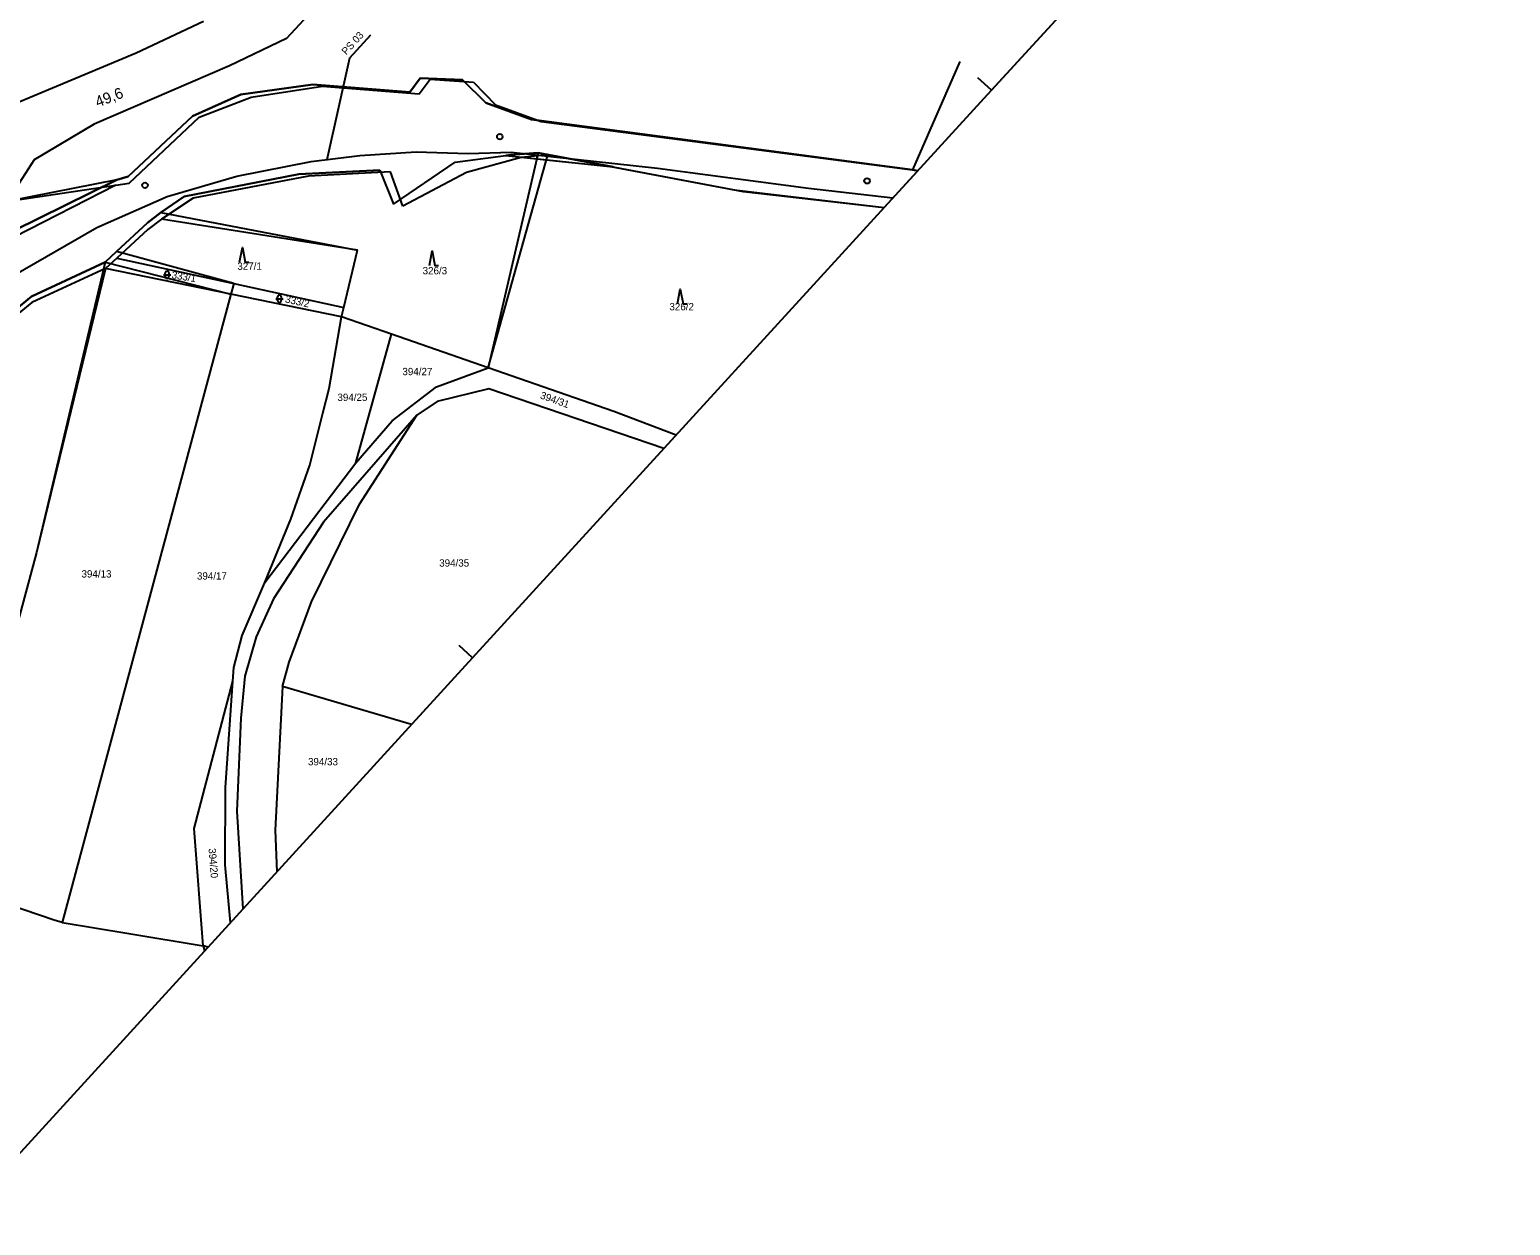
# Model space of a CAD drawing. Extents: x -678683 to -677755, y -1006946 to -1005971.
# Drawn here: x -678159.6 to -677755.1, y -1006636.4 to -1006309.9 of the extents above; entities that cross this region are included whole.
import ezdxf

# ---------------------------------------------------------------- set-up
doc = ezdxf.new("R2010")
doc.units = 0
for name, color, linetype in [('Default', 7, 'Continuous'), ('I_2_4_předběžný_vykres - Dočasný zábor - do 1 roku - PUPFL', 7, 'Continuous'), ('I_2_4_předběžný_vykres - SŽDC', 7, 'Continuous'), ('I_2_4_předběžný_vykres - VBř', 7, 'Continuous'), ('kilometráž - Vrstva 7', 7, 'Continuous'), ('koor - SSZT_nové', 7, 'Continuous'), ('MapaKN - Mladejov+Strelec_dosavani+nova_situace - Vrstva 1', 7, 'Continuous'), ('MapaKN - Mladejov+Strelec_dosavani+nova_situace - Vrstva 11', 7, 'Continuous'), ('MapaKN - Mladejov+Strelec_dosavani+nova_situace - Vrstva 18', 7, 'Continuous'), ('MapaKN - Mladejov+Strelec_dosavani+nova_situace - Vrstva 25', 7, 'Continuous'), ('MapaKN - původní vrstava 1', 7, 'Continuous'), ('popis', 7, 'Continuous'), ('ramy - Sekce lichá', 7, 'Continuous'), ('rozpiska - rámy', 7, 'Continuous')]:
    doc.layers.add(name, color=color, linetype=linetype)

msp = doc.modelspace()

# ---------------------------------------------------------------- linework, layer by layer
at = {"layer": 'Default'}
msp.add_line((-677896.87, -1006326.45), (-677755.13, -1006171.5), dxfattribs=at)
at = {"layer": 'I_2_4_předběžný_vykres - Dočasný zábor - do 1 roku - PUPFL'}
for p, q in [((-678028.13, -1006344.03), (-678029.55, -1006344.22)), ((-678020.64, -1006343.54), (-678028.13, -1006344.03)), ((-678021.01, -1006345.14), (-678020.64, -1006343.54)), ((-678020.64, -1006343.54), (-678021.01, -1006345.14)), ((-678000.24, -1006347.39), (-678020.64, -1006343.54)), ((-678029.55, -1006344.22), (-678021.01, -1006345.14)), ((-678021.01, -1006345.14), (-678000.24, -1006347.39))]:
    msp.add_line(p, q, dxfattribs=at)
msp.add_lwpolyline([(-678029.55, -1006344.22), (-678000.24, -1006347.39)], dxfattribs=at)
at = {"layer": 'I_2_4_předběžný_vykres - SŽDC'}
for p, q in [((-678052.89, -1006323.12), (-678055.78, -1006326.94)), ((-678041.39, -1006323.57), (-678052.89, -1006323.12)), ((-678034.98, -1006329.89), (-678041.39, -1006323.57)), ((-678101.88, -1006327.62), (-678115.07, -1006333.55)), ((-678082.23, -1006324.86), (-678101.88, -1006327.62)), ((-678055.78, -1006326.94), (-678082.23, -1006324.86)), ((-678022.51, -1006334.41), (-678034.98, -1006329.89)), ((-678115.07, -1006333.55), (-678132.64, -1006350.02)), ((-677918.4, -1006348.18), (-678022.51, -1006334.41)), ((-678043.36, -1006346.1), (-678028.13, -1006344.03)), ((-678028.13, -1006344.03), (-678020.64, -1006343.54)), ((-678020.64, -1006343.54), (-677967.17, -1006353.62)), ((-678060.24, -1006357.55), (-678043.36, -1006346.1)), ((-677916.96, -1006348.41), (-677918.4, -1006348.18)), ((-678135.76, -1006350.92), (-678163.98, -1006364.86)), ((-678132.64, -1006350.02), (-678135.76, -1006350.92)), ((-678117.34, -1006355.48), (-678086.04, -1006349.39)), ((-678086.04, -1006349.39), (-678063.96, -1006348.27)), ((-678063.96, -1006348.27), (-678060.24, -1006357.55)), ((-677926.18, -1006358.49), (-677916.96, -1006348.41)), ((-678123.78, -1006359.86), (-678117.34, -1006355.48)), ((-677967.17, -1006353.62), (-677926.18, -1006358.49)), ((-678127.43, -1006362.62), (-678123.78, -1006359.86)), ((-678135.88, -1006370.51), (-678127.43, -1006362.62)), ((-678138.95, -1006373.37), (-678135.88, -1006370.51)), ((-678159.12, -1006382.74), (-678138.95, -1006373.37)), ((-678187.52, -1006406.01), (-678159.12, -1006382.74))]:
    msp.add_line(p, q, dxfattribs=at)
at = {"layer": 'I_2_4_předběžný_vykres - VBř'}
msp.add_lwpolyline([(-678029.55, -1006344.22), (-678000.24, -1006347.39), (-678020.64, -1006343.54)], close=True, dxfattribs=at)
at = {"layer": 'kilometráž - Vrstva 7'}
for centre in [(-678031.17, -1006339.12), (-678128.06, -1006352.39), (-677930.85, -1006351.19)]:
    msp.add_circle(centre, 0.75, dxfattribs=at)
at = {"layer": 'koor - SSZT_nové'}
msp.add_lwpolyline([(-678199.43, -1006408.27), (-678188.69, -1006396.92), (-678166.33, -1006378.36), (-678141.21, -1006363.9), (-678122.02, -1006355.42), (-678102.99, -1006349.89), (-678082.69, -1006345.92), (-678069.35, -1006344.3), (-678054.02, -1006343.3), (-678039.76, -1006343.69), (-678028.1, -1006343.37), (-677988.11, -1006347.69), (-677946.88, -1006353.16), (-677923.77, -1006355.85)], dxfattribs=at)
at = {"layer": 'MapaKN - Mladejov+Strelec_dosavani+nova_situace - Vrstva 1'}
for points in [[(-678078.93, -1006300.97), (-678089.46, -1006312.29)], [(-678112.1, -1006307.67), (-678130.46, -1006316.3)], [(-678089.46, -1006312.29), (-678105.02, -1006319.82)], [(-678130.46, -1006316.3), (-678180.18, -1006337.1)], [(-678105.02, -1006319.82), (-678141.98, -1006335.73)], [(-677905.49, -1006318.57), (-677918.4, -1006348.18)], [(-678141.98, -1006335.73), (-678158.36, -1006345.46)], [(-678158.36, -1006345.46), (-678162.46, -1006351.78)], [(-677918.4, -1006348.18), (-677916.96, -1006348.41)], [(-678073.77, -1006385.75), (-678070.06, -1006370.08)], [(-678103.81, -1006379.22), (-678104.6, -1006382.15)], [(-678103.81, -1006379.22), (-678073.77, -1006385.75)], [(-678104.6, -1006382.15), (-678150.72, -1006553.63)], [(-678074.39, -1006388.34), (-678104.6, -1006382.15)], [(-678077.74, -1006407.83), (-678074.39, -1006388.34)], [(-678074.39, -1006388.34), (-678073.77, -1006385.75)], [(-678060.76, -1006393.07), (-678074.39, -1006388.34)], [(-678070.46, -1006428.16), (-678060.76, -1006393.07)], [(-678034.32, -1006402.24), (-678060.76, -1006393.07)], [(-678048.48, -1006407.43), (-678034.32, -1006402.24)], [(-678000, -1006414.15), (-678034.32, -1006402.24)], [(-678079.52, -1006414.56), (-678077.74, -1006407.83)], [(-678060.57, -1006416.67), (-678048.48, -1006407.43)], [(-678034.19, -1006407.98), (-678048.29, -1006411.44)], [(-677986.33, -1006424.24), (-678034.19, -1006407.98)], [(-678048.29, -1006411.44), (-678053.78, -1006415.18)], [(-678083.07, -1006428.79), (-678079.52, -1006414.56)], [(-678053.78, -1006415.18), (-678079.32, -1006444.33)], [(-678070.46, -1006428.16), (-678060.57, -1006416.67)], [(-678069.44, -1006439.48), (-678053.78, -1006415.18)], [(-677982.96, -1006420.57), (-678000, -1006414.15)], [(-678095.31, -1006460.84), (-678070.46, -1006428.16)], [(-678088.28, -1006443.53), (-678083.07, -1006428.79)], [(-678082.58, -1006466.13), (-678069.44, -1006439.48)], [(-678095.31, -1006460.84), (-678088.28, -1006443.53)], [(-678079.32, -1006444.33), (-678092.98, -1006465.3)], [(-678157.68, -1006452.66), (-678182.07, -1006543.07)], [(-678101.52, -1006475.32), (-678095.31, -1006460.84)], [(-678092.98, -1006465.3), (-678097.72, -1006475.69)], [(-678088.72, -1006482.62), (-678082.58, -1006466.13)], [(-678103.84, -1006484.04), (-678101.52, -1006475.32)], [(-678097.72, -1006475.69), (-678100.8, -1006486.38)], [(-678104.1, -1006487.79), (-678103.84, -1006484.04)], [(-678090.56, -1006489.19), (-678088.72, -1006482.62)], [(-678114.62, -1006528.01), (-678104.1, -1006487.79)], [(-678106.13, -1006516.77), (-678104.1, -1006487.79)], [(-678100.8, -1006486.38), (-678101.88, -1006497.89)], [(-678090.56, -1006489.19), (-678092.52, -1006528.43)], [(-678055.31, -1006499.65), (-678090.56, -1006489.19)], [(-678101.88, -1006497.89), (-678102.96, -1006523.31)], [(-678106.14, -1006537.95), (-678106.13, -1006516.77)], [(-678102.96, -1006523.31), (-678101.31, -1006549.94)], [(-678112.16, -1006560.07), (-678114.62, -1006528.01)], [(-678092.52, -1006528.43), (-678092.09, -1006539.86)], [(-678104.68, -1006553.63), (-678106.14, -1006537.95)], [(-678152.85, -1006553.07), (-678182.07, -1006543.07)], [(-678150.72, -1006553.63), (-678152.85, -1006553.07)], [(-678150.72, -1006553.63), (-678132.51, -1006556.69)], [(-678132.51, -1006556.69), (-678112.16, -1006560.07)], [(-678110.84, -1006560.36), (-678112.16, -1006560.07)], [(-678112.16, -1006560.07), (-678111.79, -1006561.4)]]:
    msp.add_lwpolyline(points, dxfattribs=at)
at = {"layer": 'MapaKN - Mladejov+Strelec_dosavani+nova_situace - Vrstva 11'}
msp.add_line((-678138.95, -1006373.37), (-678157.68, -1006452.66), dxfattribs=at)
for points in [[(-678055.78, -1006326.94), (-678052.89, -1006323.12)], [(-678052.89, -1006323.12), (-678041.39, -1006323.57)], [(-678041.39, -1006323.57), (-678034.98, -1006329.89)], [(-678115.07, -1006333.55), (-678101.88, -1006327.62)], [(-678101.88, -1006327.62), (-678082.23, -1006324.86)], [(-678082.23, -1006324.86), (-678055.78, -1006326.94)], [(-678034.98, -1006329.89), (-678022.51, -1006334.41)], [(-678132.64, -1006350.02), (-678115.07, -1006333.55)], [(-678022.51, -1006334.41), (-677918.4, -1006348.18)], [(-678043.36, -1006346.1), (-678028.13, -1006344.03)], [(-678020.64, -1006343.54), (-678034.32, -1006402.24)], [(-678028.13, -1006344.03), (-678020.64, -1006343.54)], [(-678020.64, -1006343.54), (-677967.17, -1006353.62)], [(-678060.24, -1006357.55), (-678043.36, -1006346.1)], [(-678135.76, -1006350.92), (-678165.35, -1006356.69)], [(-678163.98, -1006364.86), (-678135.76, -1006350.92)], [(-678135.76, -1006350.92), (-678132.64, -1006350.02)], [(-678086.04, -1006349.39), (-678117.34, -1006355.48)], [(-678063.96, -1006348.27), (-678086.04, -1006349.39)], [(-678063.96, -1006348.27), (-678060.24, -1006357.55)], [(-678117.34, -1006355.48), (-678123.78, -1006359.86)], [(-677967.17, -1006353.62), (-677926.18, -1006358.49)], [(-678123.78, -1006359.86), (-678127.43, -1006362.62)], [(-678123.78, -1006359.86), (-678070.06, -1006370.08)], [(-678127.43, -1006362.62), (-678135.88, -1006370.51)], [(-678135.88, -1006370.51), (-678138.95, -1006373.37)], [(-678103.81, -1006379.22), (-678135.88, -1006370.51)], [(-678138.95, -1006373.37), (-678159.12, -1006382.74)], [(-678138.95, -1006373.37), (-678104.6, -1006382.15)], [(-678159.12, -1006382.74), (-678187.52, -1006406.01)]]:
    msp.add_lwpolyline(points, dxfattribs=at)
at = {"layer": 'MapaKN - Mladejov+Strelec_dosavani+nova_situace - Vrstva 25'}
for points in [[(-678102.22, -1006373.39), (-678101.47, -1006369.39), (-678100.72, -1006373.39), (-678099.72, -1006373.39)], [(-678050.38, -1006374.27), (-678049.63, -1006370.27), (-678048.88, -1006374.27), (-678047.88, -1006374.27)], [(-678122.52, -1006377.31), (-678122.52, -1006376.31)], [(-678121.52, -1006376.31), (-678121.52, -1006377.31)], [(-678123.02, -1006376.81), (-678121.02, -1006376.81)], [(-678092.34, -1006383.35), (-678090.34, -1006383.35)], [(-678091.84, -1006383.85), (-678091.84, -1006382.85)], [(-678090.84, -1006382.85), (-678090.84, -1006383.85)], [(-677982.62, -1006384.79), (-677981.87, -1006380.79), (-677981.12, -1006384.79), (-677980.12, -1006384.79)]]:
    msp.add_lwpolyline(points, dxfattribs=at)
for centre, start, end in [((-678122.02, -1006376.31), 0.101, 180.0014), ((-678122.02, -1006377.31), 180.1024, 0.0029), ((-678091.34, -1006382.85), 0.101, 180.0014), ((-678091.34, -1006383.85), 180.1024, 0.0029)]:
    msp.add_arc(centre, 0.5, start, end, dxfattribs=at)
at = {"layer": 'MapaKN - původní vrstava 1'}
for points in [[(-678053.15, -1006327.44), (-678050.16, -1006323.4)], [(-678050.16, -1006323.4), (-678038.33, -1006324.2)], [(-678099.09, -1006328.36), (-678079.6, -1006325.34)], [(-678079.6, -1006325.34), (-678053.15, -1006327.44)], [(-678038.33, -1006324.2), (-678032.36, -1006330.42)], [(-678113.24, -1006333.77), (-678099.09, -1006328.36)], [(-678032.36, -1006330.42), (-678019.89, -1006334.95)], [(-678132.43, -1006351.8), (-678113.24, -1006333.77)], [(-678019.89, -1006334.95), (-677918.4, -1006348.18)], [(-678034.32, -1006402.24), (-678018.03, -1006344.08)], [(-678018.03, -1006344.08), (-678025.34, -1006344.76)], [(-677964.57, -1006354.22), (-678018.03, -1006344.08)], [(-678025.34, -1006344.76), (-678040.3, -1006348.88)], [(-678136.03, -1006352.33), (-678132.43, -1006351.8)], [(-678083.44, -1006349.86), (-678114.88, -1006355.95)], [(-678061.01, -1006348.73), (-678083.44, -1006349.86)], [(-678057.65, -1006358.05), (-678061.01, -1006348.73)], [(-678040.3, -1006348.88), (-678057.65, -1006358.05)], [(-678165.35, -1006356.69), (-678136.03, -1006352.33)], [(-678136.03, -1006352.33), (-678163.82, -1006366.54)], [(-678114.88, -1006355.95), (-678123.6, -1006361.67)], [(-677926.2, -1006358.52), (-677964.57, -1006354.22)], [(-678123.6, -1006361.67), (-678127.26, -1006364.42)], [(-678070.06, -1006370.08), (-678123.6, -1006361.67)], [(-678127.26, -1006364.42), (-678135.74, -1006372.28)], [(-678135.74, -1006372.28), (-678138.82, -1006375.13)], [(-678135.74, -1006372.28), (-678103.81, -1006379.22)], [(-678138.82, -1006375.13), (-678159.02, -1006384.43)], [(-678138.82, -1006375.13), (-678157.68, -1006452.66)], [(-678104.6, -1006382.15), (-678138.82, -1006375.13)], [(-678159.02, -1006384.43), (-678187.49, -1006407.61)]]:
    msp.add_lwpolyline(points, dxfattribs=at)
at = {"layer": 'popis'}
msp.add_lwpolyline([(-678078.33, -1006345.36), (-678072.1, -1006317.57), (-678066.39, -1006311.33)], dxfattribs=at)
at = {"layer": 'ramy - Sekce lichá'}
for p, q in [((-677896.87, -1006326.45), (-677755.13, -1006171.5)), ((-677896.87, -1006326.45), (-677900.56, -1006323.08)), ((-678038.61, -1006481.4), (-677896.87, -1006326.45)), ((-678180.35, -1006636.35), (-678038.61, -1006481.4)), ((-678038.61, -1006481.4), (-678042.3, -1006478.03))]:
    msp.add_line(p, q, dxfattribs=at)
at = {"layer": 'rozpiska - rámy'}
for p, q in [((-677755.13, -1006171.5), (-677896.87, -1006326.45)), ((-677896.87, -1006326.45), (-677755.13, -1006171.5))]:
    msp.add_line(p, q, dxfattribs=at)

# ---------------------------------------------------------------- texts
at = {"layer": 'kilometráž - Vrstva 7'}
msp.add_text('49,6', height=3, rotation=20.983, dxfattribs=at).set_placement((-678140.99, -1006331.14))
at = {"layer": 'MapaKN - Mladejov+Strelec_dosavani+nova_situace - Vrstva 18'}
for s, rotation, p in [('333/1', 350.6028, (-678120.9, -1006377.77)), ('333/2', 347.7028, (-678089.93, -1006384.35)), ('394/31', 340.4027, (-678020.31, -1006410.53)), ('394/20', 274.6022, (-678110.72, -1006533.47))]:
    msp.add_text(s, height=2, rotation=rotation, dxfattribs=at).set_placement(p)
for s, p in [('327/1', (-678102.85, -1006375.47)), ('326/3', (-678052.24, -1006376.7)), ('326/2', (-677984.83, -1006386.52)), ('394/27', (-678057.76, -1006404.24)), ('394/25', (-678075.51, -1006411.27)), ('394/13', (-678145.41, -1006459.48)), ('394/35', (-678047.71, -1006456.5)), ('394/17', (-678113.88, -1006460.04)), ('394/33', (-678083.55, -1006510.75))]:
    msp.add_text(s, height=2, dxfattribs=at).set_placement(p)
at = {"layer": 'popis'}
msp.add_text('PS 03', height=2, rotation=47.5497, dxfattribs=at).set_placement((-678073.1, -1006316.93))

doc.saveas('drawing.dxf')
